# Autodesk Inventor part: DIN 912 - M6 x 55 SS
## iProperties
IsCustomPart: 1
Created: 2006-02
Part Number: DIN 912 - M6 x 55 SS
Material: Stainless Steel
Description: Cylinder Head Cap Screw
Document SubType Name: Modeling
Standard: DIN 912
Designer: Andy Moles
Standards Organization: DIN
Language: en-US
Size Designation: M6 x 55
Categories: <MemberInstance><Categories><Category DisplayName="Fasteners" InternalName="e4da775c-781d-43d5-af7c-5136215cf5a6" Mnemonic="FSTN"><Category DisplayName="Bolts"
Mass: 15.6878 g
Surface Area: 14.2464 cm^2
Volume: 1.94156 cm^3
Density: 8.08 g/cm^3
Author: Andy Moles
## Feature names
1. Body [Revolution]
2. Slot [Extrusion]
3. Fillet1
4. Chamfer1
